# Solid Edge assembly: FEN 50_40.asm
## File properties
Title: Zylinder
Author: bmolnar
Template: iso assembly.asm
Last saved by: bmolnar
Revision: 16
Application: Solid Edge
Username: bmolnar
Dokumentum tartalom típus: 1
Document Number: FEN 50/40
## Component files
Kit_1.par
Profilrohr.par
Kit_2.par
Kolbenstange.par
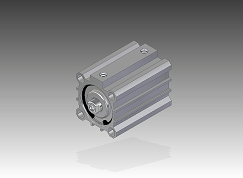
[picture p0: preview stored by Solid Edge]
